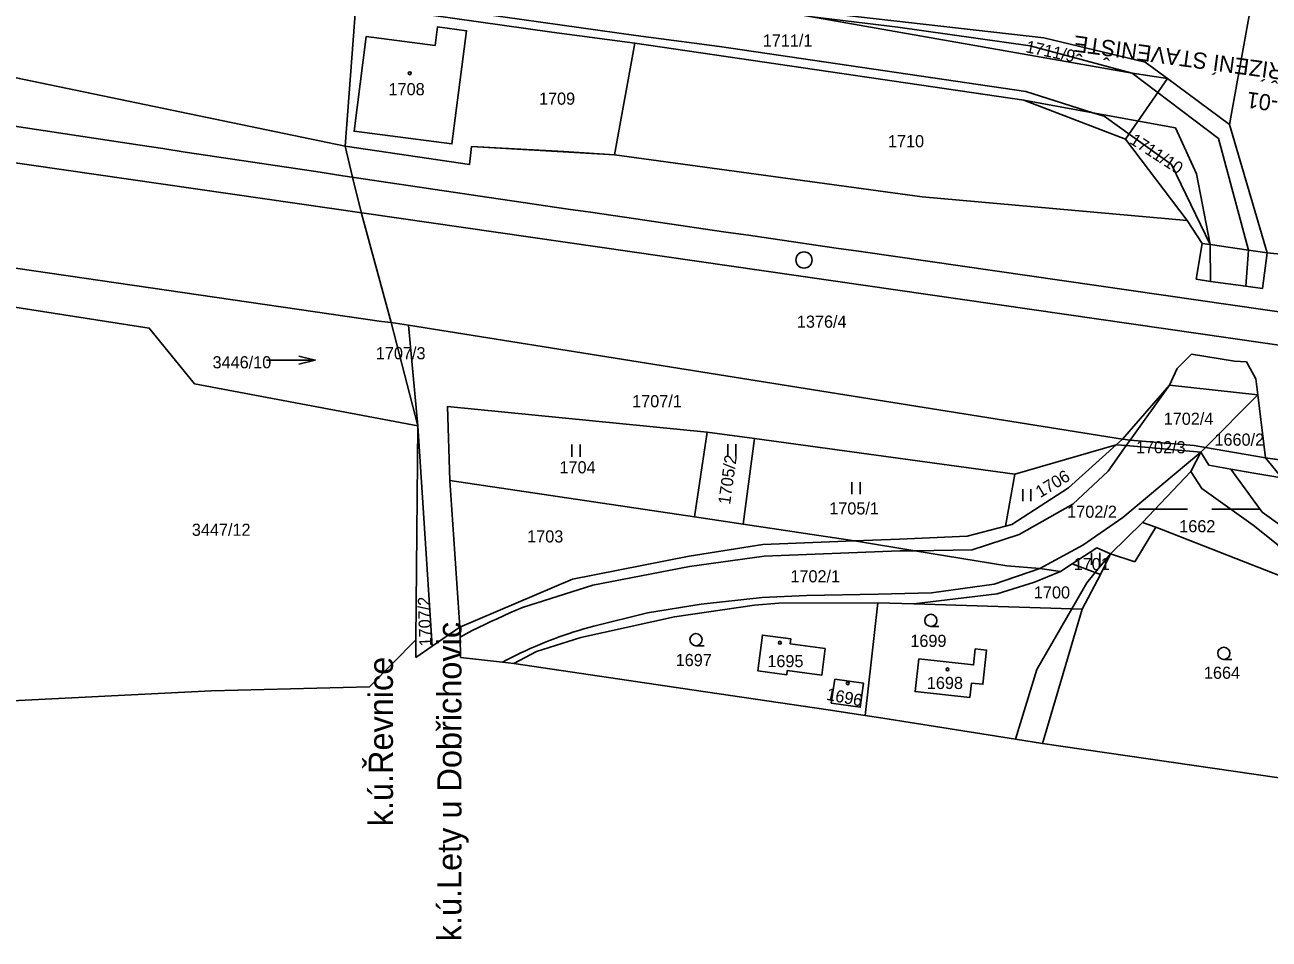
# Model space of a CAD drawing. Extents: x -757895 to -757311, y -1060303 to -1059942.
# Drawn here: x -757679.5 to -757525.7, y -1060222.2 to -1060109.2 of the extents above; entities that cross this region are included whole.
import ezdxf

# ---------------------------------------------------------------- set-up
doc = ezdxf.new("R2010")
doc.units = 0
for name, color, linetype in [('_SO 102 hektometry', 7, 'Continuous'), ('Dočasné zábory', 7, 'Continuous'), ('Dočasné zábory - čísla', 7, 'Continuous'), ('Pozemky SŽDC', 7, 'Continuous'), ('Vrstva 1', 7, 'Continuous'), ('Vrstva 53', 7, 'Continuous'), ('Vrstva 55', 7, 'Continuous'), ('Vrstva 56', 7, 'Continuous'), ('Vrstva 57', 7, 'Continuous'), ('Vrstva 58', 7, 'Continuous'), ('Vrstva 59', 7, 'Continuous')]:
    doc.layers.add(name, color=color, linetype=linetype)

msp = doc.modelspace()

# ---------------------------------------------------------------- linework, layer by layer
at = {"layer": '_SO 102 hektometry'}
msp.add_circle((-757583.22, -1060138.24), 1, dxfattribs=at)
at = {"layer": 'Dočasné zábory'}
msp.add_lwpolyline([(-757535.86, -1060133.35), (-757543.49, -1060123.29), (-757538.3, -1060115.83), (-757530.66, -1060121.48), (-757525.99, -1060137.35), (-757528.28, -1060137.03), (-757533.01, -1060136.32), (-757534.03, -1060136.19)], close=True, dxfattribs=at)
at = {"layer": 'Pozemky SŽDC'}
for points in [[(-757419.22, -1060153.71), (-757450.04, -1060148.6), (-757493.93, -1060141.33), (-757496.99, -1060140.91), (-757515.4, -1060138.37), (-757520.85, -1060137.84), (-757523.49, -1060137.59), (-757525.99, -1060137.35), (-757528.28, -1060137.03), (-757533.01, -1060136.32), (-757534.03, -1060136.19), (-757535.86, -1060133.35), (-757568.62, -1060130.44), (-757606.63, -1060125.23), (-757624.32, -1060124.22), (-757624.54, -1060126.42), (-757639.93, -1060124.17), (-757687.19, -1060114.38)], [(-757686.64, -1060138.39), (-757635.44, -1060145.86), (-757634.26, -1060145.96), (-757632.1, -1060146.3), (-757543.88, -1060160.4), (-757542.9, -1060160.49), (-757535.01, -1060161.18), (-757533.6, -1060161.43), (-757526.21, -1060162.71), (-757513.1, -1060164.5), (-757470.38, -1060167.04), (-757443.58, -1060171.99)]]:
    msp.add_lwpolyline(points, dxfattribs=at)
at = {"layer": 'Vrstva 1'}
for p, q in [((-757429.32, -1060162.53), (-757720.62, -1060120.47)), ((-757665.26, -1060124.05), (-757689.98, -1060120.32)), ((-757576.18, -1060137.2), (-757470.2, -1060152.45))]:
    msp.add_line(p, q, dxfattribs=at)
msp.add_arc((-755796.09, -1047764.6), 12500, 261.400126, 261.812855, dxfattribs=at)
at = {"layer": 'Vrstva 53'}
for points in [[(-757687.19, -1060114.38), (-757639.93, -1060124.17), (-757624.54, -1060126.42), (-757624.32, -1060124.22), (-757612.89, -1060124.84), (-757606.63, -1060125.23), (-757568.62, -1060130.44), (-757535.86, -1060133.35), (-757534.03, -1060136.19), (-757533.01, -1060136.32), (-757528.28, -1060137.03), (-757525.99, -1060137.35), (-757523.49, -1060137.59), (-757520.85, -1060137.84), (-757515.4, -1060138.37), (-757496.99, -1060140.91), (-757493.93, -1060141.33), (-757450.04, -1060148.6), (-757417.66, -1060153.97), (-757412.43, -1060151.61), (-757391.89, -1060154.81), (-757390.25, -1060143), (-757387.56, -1060158.16)], [(-757328.56, -1060183.46), (-757338.29, -1060184.85), (-757361.91, -1060181.63), (-757443.58, -1060171.99), (-757470.38, -1060167.04), (-757513.1, -1060164.5), (-757526.21, -1060162.71), (-757533.6, -1060161.43), (-757535.01, -1060161.18), (-757542.9, -1060160.49), (-757543.88, -1060160.4), (-757632.1, -1060146.3), (-757634.26, -1060145.96), (-757635.44, -1060145.86), (-757686.64, -1060138.39), (-757693.18, -1060137.43), (-757732.62, -1060131.67), (-757793.56, -1060122.78), (-757866, -1060118.97)]]:
    msp.add_lwpolyline(points, dxfattribs=at)
at = {"layer": 'Vrstva 55'}
for p, q in [((-757530.66, -1060121.48), (-757527.8, -1060105.72)), ((-757638.59, -1060106.69), (-757639.93, -1060124.17)), ((-757638.59, -1060106.69), (-757639.93, -1060124.17)), ((-757606.63, -1060125.23), (-757604.11, -1060111.45)), ((-757556.06, -1060118.47), (-757604.11, -1060111.45)), ((-757687.19, -1060114.38), (-757639.93, -1060124.17)), ((-757530.66, -1060121.48), (-757538.3, -1060115.83)), ((-757525.99, -1060137.35), (-757530.66, -1060121.48)), ((-757634.26, -1060145.96), (-757632.1, -1060146.3)), ((-757634.26, -1060145.96), (-757630.94, -1060158.73)), ((-757634.26, -1060145.96), (-757630.94, -1060158.73)), ((-757632.1, -1060146.3), (-757543.88, -1060160.4)), ((-757632.1, -1060146.3), (-757630.94, -1060158.73)), ((-757527.15, -1060154.92), (-757533.6, -1060161.43)), ((-757527.15, -1060154.92), (-757526.21, -1060162.71)), ((-757630.94, -1060158.73), (-757631.18, -1060185.19)), ((-757630.94, -1060158.73), (-757631.18, -1060185.19)), ((-757630.94, -1060158.73), (-757629.16, -1060185.96)), ((-757596.77, -1060170), (-757595.21, -1060159.51)), ((-757589.33, -1060160.31), (-757595.21, -1060159.51)), ((-757589.33, -1060160.31), (-757590.73, -1060170.9)), ((-757557.15, -1060164.71), (-757589.33, -1060160.31)), ((-757544.63, -1060161.07), (-757557.15, -1060164.71)), ((-757543.88, -1060160.4), (-757544.63, -1060161.07)), ((-757533.6, -1060161.43), (-757534.18, -1060162.01)), ((-757533.6, -1060161.43), (-757526.21, -1060162.71)), ((-757534.18, -1060162.01), (-757535.4, -1060164.4)), ((-757526.21, -1060162.71), (-757513.1, -1060164.5)), ((-757535.4, -1060164.4), (-757541.4, -1060170.7)), ((-757627, -1060165.49), (-757625.74, -1060183.63)), ((-757596.77, -1060170), (-757627, -1060165.49)), ((-757558.32, -1060171.12), (-757557.15, -1060164.71)), ((-757590.73, -1060170.9), (-757596.77, -1060170)), ((-757541.4, -1060170.7), (-757545.33, -1060174.55)), ((-757576.99, -1060172.95), (-757590.73, -1060170.9)), ((-757545.33, -1060174.55), (-757546.6, -1060177.1)), ((-757550.1, -1060175.8), (-757551.51, -1060176.74)), ((-757546.6, -1060177.1), (-757548.85, -1060181.4)), ((-757575.67, -1060194.52), (-757574.09, -1060180.62)), ((-757569.63, -1060180.73), (-757574.09, -1060180.62)), ((-757548.85, -1060181.4), (-757553.73, -1060197.99)), ((-757625.74, -1060183.63), (-757629.16, -1060185.96)), ((-757631.18, -1060185.19), (-757636.9, -1060190.98)), ((-757631.18, -1060185.19), (-757631.2, -1060187.35)), ((-757629.16, -1060185.96), (-757631.2, -1060187.35)), ((-757596.81, -1060191.42), (-757619.09, -1060188.12)), ((-757580.24, -1060193.85), (-757596.81, -1060191.42)), ((-757575.67, -1060194.52), (-757580.24, -1060193.85)), ((-757553.73, -1060197.99), (-757501.45, -1060205.62))]:
    msp.add_line(p, q, dxfattribs=at)
for points in [[(-757643.18, -1060052.41), (-757642.66, -1060069.92), (-757642.17, -1060087.53), (-757638.59, -1060106.69), (-757639.93, -1060124.17), (-757639.03, -1060128.02), (-757637.9, -1060132.49), (-757634.26, -1060145.96), (-757630.94, -1060158.73), (-757631.18, -1060185.19), (-757631.2, -1060187.35)], [(-757604.11, -1060111.45), (-757614.37, -1060110.07), (-757635.45, -1060107.13)], [(-757538.3, -1060115.83), (-757542.65, -1060115.17), (-757582.51, -1060108.15), (-757593.23, -1060106.29)], [(-757538.3, -1060115.83), (-757541.05, -1060113.79), (-757553.6, -1060110.8), (-757593.23, -1060106.29)], [(-757637.32, -1060110.63), (-757638.83, -1060122.33), (-757626.73, -1060123.9), (-757624.93, -1060109.9), (-757628.52, -1060109.44), (-757628.82, -1060111.73), (-757637.32, -1060110.63)], [(-757535.86, -1060133.35), (-757543.49, -1060123.29), (-757556.06, -1060118.47)], [(-757556.06, -1060118.47), (-757547.51, -1060120.04), (-757537.32, -1060121.92), (-757534.73, -1060127.58), (-757533.01, -1060136.32)], [(-757606.63, -1060125.23), (-757612.89, -1060124.84), (-757624.32, -1060124.22), (-757624.54, -1060126.42), (-757639.93, -1060124.17)], [(-757639.93, -1060124.17), (-757639.03, -1060128.02), (-757637.9, -1060132.49), (-757634.26, -1060145.96)], [(-757639.93, -1060124.17), (-757639.03, -1060128.02), (-757637.9, -1060132.49), (-757634.26, -1060145.96)], [(-757535.86, -1060133.35), (-757568.62, -1060130.44), (-757606.63, -1060125.23)], [(-757533.01, -1060136.32), (-757534.03, -1060136.19), (-757535.86, -1060133.35)], [(-757525.99, -1060137.35), (-757528.28, -1060137.03), (-757533.01, -1060136.32)], [(-757634.26, -1060145.96), (-757635.44, -1060145.86), (-757686.64, -1060138.39)], [(-757515.4, -1060138.37), (-757518.94, -1060138.03), (-757520.85, -1060137.84), (-757523.49, -1060137.59), (-757525.99, -1060137.35)], [(-757686.61, -1060143.18), (-757664.14, -1060146.65), (-757658.56, -1060153.53), (-757630.94, -1060158.73)], [(-757543.88, -1060160.4), (-757538.07, -1060153.7), (-757527.15, -1060154.92)], [(-757595.21, -1060159.51), (-757627.27, -1060156.33), (-757627, -1060165.49)], [(-757544.63, -1060161.07), (-757550.52, -1060166.39), (-757557.55, -1060170.92), (-757558.32, -1060171.12)], [(-757534.18, -1060162.01), (-757543.4, -1060161.18), (-757544.63, -1060161.07)], [(-757533.6, -1060161.43), (-757535.01, -1060161.18), (-757542.9, -1060160.49), (-757543.88, -1060160.4)], [(-757530.47, -1060164.08), (-757533.19, -1060163.6), (-757534.18, -1060162.01)], [(-757535.4, -1060164.4), (-757534.05, -1060166.5), (-757527.72, -1060171), (-757524.67, -1060173.45), (-757522.06, -1060178.2)], [(-757530.47, -1060164.08), (-757526.6, -1060169.42), (-757519.47, -1060174.52), (-757512.04, -1060178.07), (-757508.94, -1060181.82), (-757502, -1060190.6), (-757494.7, -1060204.13)], [(-757512.14, -1060167.1), (-757524.18, -1060165.15), (-757527.62, -1060164.59), (-757530.47, -1060164.08)], [(-757541.4, -1060170.7), (-757539.76, -1060171.25), (-757522.06, -1060178.2)], [(-757558.32, -1060171.12), (-757563.04, -1060172.38), (-757571.43, -1060172.73), (-757576.99, -1060172.95)], [(-757576.99, -1060172.95), (-757588.33, -1060173.41), (-757597.42, -1060174.85), (-757611.84, -1060177.68), (-757625.74, -1060183.63)], [(-757551.51, -1060176.74), (-757554.09, -1060176.38), (-757558.16, -1060176.02), (-757569.54, -1060174.17), (-757576.99, -1060172.95)], [(-757545.33, -1060174.55), (-757547.04, -1060173.83), (-757550.1, -1060175.8)], [(-757551.51, -1060176.74), (-757554.73, -1060178.07), (-757559.36, -1060179.48), (-757569.63, -1060180.73)], [(-757546.6, -1060177.1), (-757547.24, -1060176.86), (-757550.1, -1060175.8)], [(-757574.09, -1060180.62), (-757586.32, -1060180.67), (-757589.35, -1060180.9), (-757599.24, -1060182.35), (-757610.82, -1060184.91), (-757616.3, -1060186.63), (-757619.09, -1060188.12)], [(-757548.85, -1060181.4), (-757550.13, -1060181.36), (-757569.63, -1060180.73)], [(-757625.74, -1060183.63), (-757625.72, -1060184.84), (-757625.67, -1060187.37)], [(-757580.59, -1060186.26), (-757584.93, -1060185.69), (-757584.85, -1060185.07), (-757588.36, -1060184.6), (-757588.94, -1060189.01), (-757585.35, -1060189.49), (-757585.29, -1060188.99), (-757581.03, -1060189.55), (-757580.59, -1060186.26)], [(-757625.67, -1060187.37), (-757620.5, -1060187.96), (-757619.09, -1060188.12)], [(-757569.05, -1060187.55), (-757569.49, -1060191.57), (-757562.71, -1060192.3), (-757562.52, -1060190.53), (-757561.12, -1060190.68), (-757560.66, -1060186.46), (-757562.06, -1060186.31), (-757562.27, -1060188.28), (-757569.05, -1060187.55)], [(-757579.43, -1060190.03), (-757579.85, -1060193), (-757576.28, -1060193.51), (-757575.85, -1060190.54), (-757579.43, -1060190.03)], [(-757684.44, -1060192.89), (-757656.46, -1060191.47), (-757636.9, -1060190.98)], [(-757553.73, -1060197.99), (-757557.09, -1060197.46), (-757573.5, -1060194.87), (-757575.67, -1060194.52)]]:
    msp.add_lwpolyline(points, dxfattribs=at)
at = {"layer": 'Vrstva 56'}
for p, q in [((-757625.12, -1060107.53), (-757604, -1060110.48)), ((-757571.64, -1060109.48), (-757582.51, -1060108.15)), ((-757604, -1060110.48), (-757593.68, -1060111.85)), ((-757555.27, -1060111.76), (-757571.64, -1060109.48)), ((-757593.68, -1060111.85), (-757555.79, -1060117.41)), ((-757555.27, -1060111.76), (-757542.65, -1060115.17)), ((-757542.65, -1060115.17), (-757532.02, -1060123.21)), ((-757555.79, -1060117.41), (-757547.51, -1060120.04)), ((-757546.14, -1060120.48), (-757547.51, -1060120.04)), ((-757546.14, -1060120.48), (-757537.81, -1060126.43)), ((-757528.28, -1060137.03), (-757532.02, -1060123.21)), ((-757537.81, -1060126.43), (-757533.01, -1060136.32)), ((-757534.76, -1060140.62), (-757534.03, -1060136.19)), ((-757533.01, -1060136.32), (-757532.98, -1060140.88)), ((-757528.61, -1060141.49), (-757528.28, -1060137.03)), ((-757525.99, -1060137.35), (-757526.57, -1060141.77)), ((-757532.98, -1060140.88), (-757534.76, -1060140.62)), ((-757528.61, -1060141.49), (-757532.98, -1060140.88)), ((-757526.57, -1060141.77), (-757528.61, -1060141.49)), ((-757535.34, -1060149.89), (-757537.11, -1060151.64)), ((-757530.01, -1060150.73), (-757535.34, -1060149.89)), ((-757530.01, -1060150.73), (-757528.53, -1060150.83)), ((-757537.11, -1060151.64), (-757538.07, -1060153.7)), ((-757528.53, -1060150.83), (-757527.39, -1060152.92)), ((-757542.9, -1060160.49), (-757538.07, -1060153.7)), ((-757527.39, -1060152.92), (-757527.15, -1060154.92)), ((-757545.65, -1060164.34), (-757543.4, -1060161.18)), ((-757543.4, -1060161.18), (-757542.9, -1060160.49)), ((-757534.18, -1060162.01), (-757543.82, -1060170.07)), ((-757526.21, -1060162.71), (-757524.18, -1060165.15)), ((-757550.01, -1060168.4), (-757545.65, -1060164.34)), ((-757556.62, -1060172.15), (-757550.01, -1060168.4)), ((-757548.76, -1060173.47), (-757543.82, -1060170.07)), ((-757562.46, -1060174.07), (-757556.62, -1060172.15)), ((-757539.76, -1060171.25), (-757542.34, -1060175.54)), ((-757554.09, -1060176.38), (-757548.76, -1060173.47)), ((-757597.39, -1060176.11), (-757588.16, -1060174.83)), ((-757588.16, -1060174.83), (-757571.4, -1060174.19)), ((-757571.4, -1060174.19), (-757569.54, -1060174.17)), ((-757569.54, -1060174.17), (-757562.46, -1060174.07)), ((-757547.24, -1060176.86), (-757545.33, -1060174.55)), ((-757542.34, -1060175.54), (-757545.33, -1060174.55)), ((-757609.33, -1060178.42), (-757597.39, -1060176.11)), ((-757559.73, -1060178.32), (-757554.09, -1060176.38)), ((-757548.27, -1060178.12), (-757547.24, -1060176.86)), ((-757618.02, -1060181.19), (-757609.33, -1060178.42)), ((-757567.48, -1060179.37), (-757559.73, -1060178.32)), ((-757548.27, -1060178.12), (-757550.13, -1060181.36)), ((-757588.4, -1060179.97), (-757595.94, -1060180.77)), ((-757582.91, -1060179.71), (-757588.4, -1060179.97)), ((-757582.91, -1060179.71), (-757574.04, -1060179.54)), ((-757574.04, -1060179.54), (-757567.48, -1060179.37)), ((-757595.94, -1060180.77), (-757602.57, -1060181.84)), ((-757550.13, -1060181.36), (-757554.44, -1060188.87)), ((-757602.57, -1060181.84), (-757609.19, -1060183.49)), ((-757554.44, -1060188.87), (-757557.09, -1060197.46))]:
    msp.add_line(p, q, dxfattribs=at)
for points in [[(-757625.72, -1060184.84), (-757624.96, -1060184.44), (-757624.21, -1060184.05), (-757623.45, -1060183.67), (-757622.68, -1060183.3), (-757621.91, -1060182.93), (-757621.14, -1060182.57), (-757620.36, -1060182.21), (-757619.59, -1060181.86), (-757618.8, -1060181.52), (-757618.02, -1060181.19)], [(-757620.5, -1060187.96), (-757619.93, -1060187.66), (-757619.36, -1060187.36), (-757618.79, -1060187.08), (-757618.21, -1060186.8), (-757617.63, -1060186.53), (-757617.05, -1060186.26), (-757616.46, -1060186), (-757615.87, -1060185.75), (-757615.28, -1060185.51), (-757614.68, -1060185.27), (-757614.08, -1060185.05), (-757613.48, -1060184.82), (-757612.87, -1060184.61), (-757612.26, -1060184.41), (-757611.65, -1060184.21), (-757611.04, -1060184.02), (-757610.43, -1060183.83), (-757609.81, -1060183.66), (-757609.19, -1060183.49)]]:
    msp.add_lwpolyline(points, dxfattribs=at)
at = {"layer": 'Vrstva 58'}
for p, q in [((-757649.63, -1060150.62), (-757643.63, -1060150.62)), ((-757611.9, -1060161.05), (-757611.9, -1060162.55)), ((-757610.9, -1060162.55), (-757610.9, -1060161.05)), ((-757592.64, -1060161.02), (-757592.64, -1060162.52)), ((-757591.64, -1060162.52), (-757591.64, -1060161.02)), ((-757577.3, -1060165.68), (-757577.3, -1060167.18)), ((-757576.3, -1060167.18), (-757576.3, -1060165.68)), ((-757556.2, -1060166.55), (-757556.2, -1060168.05)), ((-757555.2, -1060168.05), (-757555.2, -1060166.55)), ((-757541.83, -1060169.03), (-757535.83, -1060169.03)), ((-757532.83, -1060169.03), (-757526.83, -1060169.03)), ((-757547.68, -1060174.43), (-757547.68, -1060175.93)), ((-757546.68, -1060175.93), (-757546.68, -1060174.43)), ((-757567.56, -1060183.53), (-757566.56, -1060183.53)), ((-757596.57, -1060185.91), (-757595.57, -1060185.91)), ((-757531.34, -1060187.6), (-757530.34, -1060187.6))]:
    msp.add_line(p, q, dxfattribs=at)
msp.add_lwpolyline([(-757645.63, -1060150.12), (-757643.63, -1060150.62), (-757645.63, -1060151.12)], dxfattribs=at)
for centre in [(-757567.56, -1060182.78), (-757596.57, -1060185.16), (-757531.34, -1060186.85)]:
    msp.add_circle(centre, 0.75, dxfattribs=at)
at = {"layer": 'Vrstva 59'}
for centre in [(-757631.95, -1060115.17), (-757586.19, -1060185.54), (-757565.49, -1060188.83), (-757577.81, -1060190.55)]:
    msp.add_circle(centre, 0.175, dxfattribs=at)

# ---------------------------------------------------------------- texts
at = {"layer": 'Dočasné zábory - čísla'}
for s, p in [('ZAŘÍZENÍ STAVENIŠTĚ', (-757520.45, -1060114.48)), ('ZD-01', (-757520.99, -1060118.44))]:
    msp.add_text(s, height=2, rotation=172.2261, dxfattribs=at).set_placement(p)
at = {"layer": 'Vrstva 55'}
for s, p in [('k.ú.Lety u Dobřichovic', (-757625.55, -1060222.44)), ('k.ú.Řevnice', (-757634.02, -1060208.23))]:
    msp.add_text(s, height=3, rotation=90, dxfattribs=at).set_placement(p)
at = {"layer": 'Vrstva 57'}
for s, p in [('1711/1', (-757588.32, -1060111.87)), ('1708', (-757634.56, -1060117.88)), ('1709', (-757615.97, -1060119.05)), ('1710', (-757572.85, -1060124.31)), ('1376/4', (-757584.1, -1060146.61)), ('1707/3', (-757636.13, -1060150.51)), ('3446/10', (-757656.31, -1060151.63)), ('1707/1', (-757604.46, -1060156.44)), ('1702/4', (-757538.77, -1060158.61)), ('1660/2', (-757532.5, -1060161.19)), ('1702/3', (-757542.2, -1060162.13)), ('1704', (-757613.44, -1060164.61)), ('1705/1', (-757580.1, -1060169.69)), ('1702/2', (-757550.69, -1060170.1)), ('1662', (-757536.85, -1060171.89)), ('3447/12', (-757658.87, -1060172.33)), ('1703', (-757617.43, -1060173.15)), ('1701', (-757549.9, -1060176.57)), ('1702/1', (-757584.9, -1060178.08)), ('1700', (-757554.81, -1060180.07)), ('1699', (-757570.08, -1060186.06)), ('1697', (-757599.08, -1060188.43)), ('1695', (-757587.75, -1060188.56)), ('1664', (-757533.8, -1060190)), ('1698', (-757568.04, -1060191.26))]:
    msp.add_text(s, height=1.5, dxfattribs=at).set_placement(p)
for s, rotation, p in [('1711/9', 348, (-757555.9, -1060112.55)), ('1711/10', 327, (-757543.09, -1060123.76)), ('1705/2', 82, (-757592.36, -1060168.52)), ('1706', 31, (-757554.03, -1060167.68)), ('1707/2', 92, (-757629.25, -1060185.96)), ('1696', 349, (-757580.55, -1060192.58))]:
    msp.add_text(s, height=1.5, rotation=rotation, dxfattribs=at).set_placement(p)

doc.saveas('drawing.dxf')
